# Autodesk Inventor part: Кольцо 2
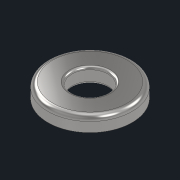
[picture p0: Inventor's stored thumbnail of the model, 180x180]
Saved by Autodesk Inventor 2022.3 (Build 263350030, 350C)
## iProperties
Created: 2022-08
Part Number: Кольцо 2
Material: Сталь 40ХНМА
Document SubType Name: Modeling
Designer: Карташов
Density: 7.85 g/cm^3
Appearance: С умеренной полировкой
Author: Карташов
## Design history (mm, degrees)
sketch "Эскиз1"
  geometry: L1 (0, 0)-(0, 20.03); L2 (15, 1.5)-(15, 10); L3 (17, 12)-(31, 12); L4 (35, 8)-(35, 0); L5 (35, 0)-(30, 0); L6 (30, 0)-(30, 7); L7 (30, 7)-(20, 7); L8 (20, 7)-(20, 1.5); L9 (18.5, 0)-(16.5, 0); A1 r 4 centre (31, 8) between (35, 8) and (31, 12); A2 r 2 centre (17, 10) between (17, 12) and (15, 10); A3 r 1.5 centre (18.5, 1.5) between (18.5, 0) and (20, 1.5); A4 r 1.5 centre (16.5, 1.5) between (15, 1.5) and (16.5, 0); 4 further points
  constraints: 18 end point, 8 point on circle, 8 tangent, 5 vertical, 4 centre point, 4 horizontal, 4 point on line, 2 horizontal alignment, 2 midpoint, 1 equal radius
  dimensions: "d0" = 30 diameter of L2 L1; "d1" = 40 diameter of point (20, 4.25) L1; "d2" = 60 diameter of point (30, 3.5) L1; "d3" = 70 diameter of L4 L1; "d4" = 7 distance of L5.end L6.end; "d5" = 12 distance of point (35, 12) L4.end; "d6" = 4 radius of A1; "d7" = 2 radius of A2; "d8" = 1.5 radius of A3 (derived)
revolve "Вращение1" sketch "Эскиз1" stored, may be unused: angle "d9" = 90 deg
node "Твердое тело1"
